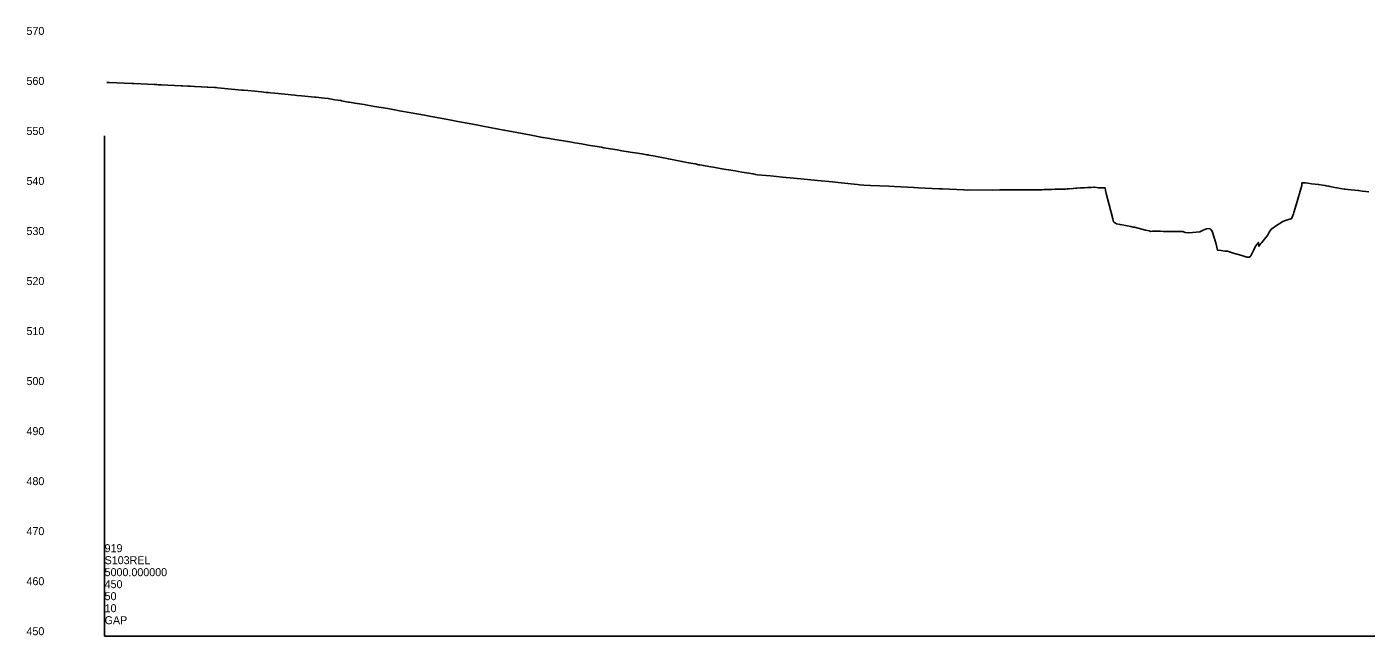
# Model space of a CAD drawing. Extents: x 49922 to 52613, y 49991 to 60509.
# Drawn here: x 49922 to 51261, y 52500 to 53109 of the extents above; entities that cross this region are included whole.
import ezdxf

# ---------------------------------------------------------------- set-up
doc = ezdxf.new("R2010")
doc.units = 0
for name, color, linetype in [('RD_DDB_ElevTX', 7, 'Continuous'), ('RD_DDB_Profile_EX', 7, 'Continuous'), ('RD_GPK_Profile_Cell', 7, 'Continuous')]:
    doc.layers.add(name, color=color, linetype=linetype)

msp = doc.modelspace()

# ---------------------------------------------------------------- linework, layer by layer
at = {"layer": 'RD_DDB_Profile_EX'}
for points in [[(50002.3, 53053.6), (50004.7, 53053.4), (50027.3, 53052.4), (50029.1, 53052.3), (50049.8, 53051.4), (50052.3, 53051.3), (50053.5, 53051.2), (50056.5, 53051.1), (50063.1, 53050.8), (50069.8, 53050.5), (50076.5, 53050.1), (50077.3, 53050.1), (50077.7, 53050.1), (50083.2, 53049.8), (50085.9, 53049.7), (50089.9, 53049.5), (50096.5, 53049.2), (50102.6, 53048.8), (50103.2, 53048.8), (50109.9, 53048.4), (50111.8, 53048.3), (50113.2, 53048.2), (50116.6, 53047.9), (50123.3, 53047.2), (50130, 53046.6), (50136.7, 53045.9), (50139.3, 53045.7), (50143.3, 53045.3), (50150, 53044.7), (50156.7, 53044), (50161.6, 53043.5), (50163.4, 53043.4), (50165.7, 53043.2), (50170, 53042.8), (50176.7, 53042.1), (50183.4, 53041.4), (50186.6, 53041.1), (50190.1, 53040.8), (50192.3, 53040.6), (50196.8, 53040.2), (50203.4, 53039.5), (50210.1, 53038.9), (50211.5, 53038.7), (50214.2, 53038.5), (50216.8, 53038.2), (50219.8, 53037.9), (50223.5, 53037.3), (50230.2, 53036.2), (50236.1, 53035.3), (50236.8, 53035.1), (50243.5, 53033.9), (50244.8, 53033.7), (50250.2, 53032.8), (50259.5, 53031.3), (50269.8, 53029.4), (50283, 53027.3), (50294.8, 53025.1), (50306.4, 53023.2), (50319.8, 53020.7), (50324.6, 53019.8), (50328.3, 53019.2), (50344.6, 53016.2), (50353.2, 53014.4), (50371.8, 53011), (50378.2, 53009.7), (50399.1, 53005.8), (50403.1, 53005), (50426.5, 53000.7), (50428.1, 53000.4), (50437.7, 52998.6), (50438.3, 52998.6), (50444.7, 52997.5), (50450, 52996.6), (50456.7, 52995.4), (50462.7, 52994.4), (50463.4, 52994.3), (50468.3, 52993.5), (50470.1, 52993.1), (50476.8, 52992), (50483.4, 52990.9), (50487.6, 52990.2), (50490.1, 52989.8), (50496.8, 52988.7), (50498.9, 52988.3), (50503.5, 52987.6), (50510.2, 52986.4), (50512.5, 52986), (50516.9, 52985.3), (50523.5, 52984.3), (50527.7, 52983.6), (50530.2, 52983.2), (50536.9, 52982.1), (50537.5, 52982), (50541.9, 52981.3), (50543.6, 52981), (50544, 52980.9), (50550.3, 52979.8), (50551.6, 52979.5), (50556.9, 52978.5), (50563.6, 52977.1), (50569, 52976.1)], [(50569, 52976.1), (50570.3, 52975.9), (50575.3, 52974.9), (50577, 52974.6), (50583.7, 52973.3), (50590.3, 52972), (50594, 52971.3), (50595, 52971.1), (50597, 52970.7), (50598.6, 52970.4), (50603.9, 52969.5), (50610.4, 52968.4), (50617.1, 52967.3), (50623.7, 52966.2), (50630.4, 52965), (50633.3, 52964.6), (50637.1, 52963.9), (50643.8, 52962.8), (50648.4, 52962), (50650.7, 52961.6), (50652.7, 52961.3), (50665.5, 52960.1), (50677.7, 52958.9), (50689.1, 52957.8), (50702.7, 52956.4), (50712.7, 52955.5), (50727.7, 52954), (50736.2, 52953.1), (50752.7, 52951.5), (50754.5, 52951.3), (50758.9, 52950.9), (50765.5, 52950.6), (50783.9, 52949.7), (50789.5, 52949.5), (50808.9, 52948.5), (50813.5, 52948.3), (50833.9, 52947.3), (50837.5, 52947.2), (50859, 52946.1), (50859.3, 52946.1), (50862.3, 52945.9), (50864.8, 52946), (50887.2, 52945.9), (50895, 52946), (50912.2, 52946), (50921.2, 52946.2), (50923.2, 52946.2), (50924.8, 52946.2), (50928.4, 52946.2), (50932, 52946.3), (50935.6, 52946.3), (50937.2, 52946.3), (50939.2, 52946.4), (50942.9, 52946.5), (50946.5, 52946.6), (50950.1, 52946.7), (50951, 52946.7), (50953.7, 52946.8), (50957.3, 52946.8), (50960.9, 52946.9), (50962.2, 52947), (50963.5, 52947), (50964.5, 52947.1), (50968.1, 52947.5), (50970.8, 52947.8), (50971.7, 52947.8), (50975.4, 52948), (50979, 52948.2), (50982.6, 52948.4), (50986.2, 52948.5), (50988.7, 52948.7), (50989.8, 52948.7), (50993.6, 52948), (50997, 52948.1), (50998.7, 52948.1), (51000, 52948.2), (51000.6, 52945.5), (51001.3, 52942.5), (51004.3, 52931.1), (51007.9, 52917.1), (51008.6, 52914.3), (51011.6, 52912.1), (51015.1, 52911.4), (51018.7, 52910.8), (51022.3, 52910.1), (51025.9, 52909.4), (51028.3, 52909), (51029.5, 52908.7), (51033.1, 52907.8), (51036.8, 52906.9), (51040.4, 52906), (51044, 52905.1), (51045.9, 52904.6), (51047.6, 52904.7), (51051.2, 52904.7), (51054.8, 52904.7), (51055.6, 52904.7), (51058.4, 52904.6), (51062, 52904.6), (51065.6, 52904.6), (51069.3, 52904.5)], [(51069.3, 52904.5), (51072.9, 52904.5), (51076.5, 52904.4), (51077.9, 52904.4), (51080.1, 52903.4), (51083.8, 52903.2), (51087.3, 52903.5), (51091.1, 52903.9), (51094.7, 52904.3), (51098.2, 52905.9), (51101.3, 52907.3), (51101.8, 52907.3), (51104.8, 52907.5), (51105.4, 52906.9), (51107, 52904.9), (51109, 52898.6), (51111.1, 52891.8), (51112.4, 52886), (51116.2, 52885.5), (51119.8, 52885), (51120.7, 52884.9), (51122.4, 52884.7), (51123.4, 52884.4), (51125.3, 52883.8), (51127, 52883.3), (51130.7, 52882.2), (51134.3, 52881.2), (51137.9, 52880.1), (51141.7, 52878.9), (51144.6, 52878.7), (51145.1, 52879.4), (51145.7, 52880.3), (51148.7, 52886.2), (51150.5, 52889.7), (51152.3, 52892.2), (51153.4, 52893.6), (51153.9, 52889.7), (51155.9, 52892.6), (51156.7, 52893.6), (51159.5, 52897), (51162.5, 52900.5), (51163.2, 52901.9), (51164.2, 52903.9), (51165.6, 52906.1), (51166.2, 52906.9), (51166.8, 52907.3), (51170.4, 52909.7), (51174, 52912.1), (51177.7, 52914.5), (51181.2, 52915.7), (51184.8, 52916.8), (51185.9, 52917.1), (51186.3, 52917.2), (51188.4, 52922.3), (51188.9, 52923.5), (51192, 52934.4), (51195.7, 52947.1), (51196.6, 52950.5), (51196.8, 52953.2), (51199.3, 52953), (51200.3, 52953), (51202.9, 52952.7), (51206.5, 52952.3), (51210.1, 52951.9), (51213.1, 52951.6), (51213.7, 52951.5), (51217.3, 52950.9), (51220.1, 52950.4), (51221, 52950.2), (51223.6, 52949.7), (51224.6, 52949.6), (51228.2, 52948.9), (51231.8, 52948.3), (51235.4, 52947.6), (51239, 52946.9), (51239.4, 52946.8), (51240, 52946.7), (51242.6, 52946.5), (51246.2, 52946.1), (51249.8, 52945.8), (51253, 52945.5), (51253.4, 52945.4), (51257.1, 52944.9), (51260.7, 52944.5), (51263.6, 52944.1)]]:
    msp.add_lwpolyline(points, dxfattribs=at)
at = {"layer": 'RD_GPK_Profile_Cell'}
for q in [(50000, 53000), (52600, 52500), (50000, 52500)]:
    msp.add_line((50000, 52500), q, dxfattribs=at)

# ---------------------------------------------------------------- texts
at = {"layer": 'RD_DDB_ElevTX'}
for s, p in [('570', (49921.9, 53101)), ('560', (49921.9, 53051)), ('550', (49921.9, 53001)), ('540', (49921.9, 52951)), ('530', (49921.9, 52901)), ('520', (49921.9, 52851)), ('510', (49921.9, 52801)), ('500', (49921.9, 52751)), ('490', (49921.9, 52701)), ('480', (49921.9, 52651)), ('470', (49921.9, 52601)), ('460', (49921.9, 52551)), ('450', (49921.9, 52501))]:
    msp.add_text(s, height=8, dxfattribs=at).set_placement(p)
at = {"layer": 'RD_GPK_Profile_Cell'}
for s, p in [('919', (50000, 52584)), ('S103REL', (50000, 52572)), ('5000.000000', (50000, 52560)), ('450', (50000, 52548)), ('50', (50000, 52536)), ('10', (50000, 52524)), ('GAP', (50000, 52512))]:
    msp.add_text(s, height=8, dxfattribs=at).set_placement(p)

doc.saveas('drawing.dxf')
